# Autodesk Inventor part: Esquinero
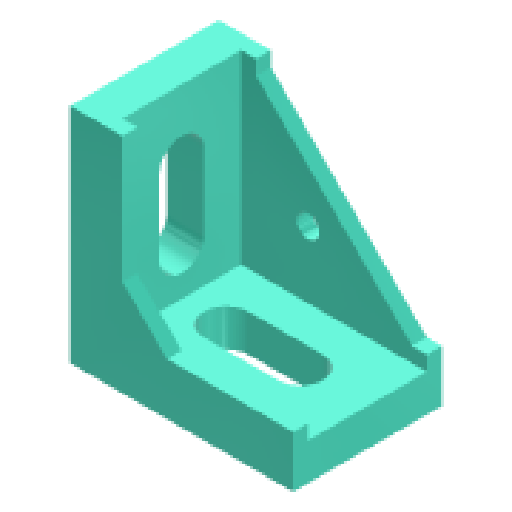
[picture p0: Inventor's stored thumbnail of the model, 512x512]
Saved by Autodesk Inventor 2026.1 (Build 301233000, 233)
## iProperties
Created: 2025-06
Part Number: Esquinero
Material: Genérico
Document SubType Name: Modeling
Designer: piero
Density: 1 g/cm^3
Appearance: Suave - Turquesa
Author: piero
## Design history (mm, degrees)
sketch "Boceto1"
  geometry: L1 (0, 0)-(30, 0); L2 (30, 0)-(30, -20); L3 (30, -20)-(0, -20); L4 (0, -20)-(0, 0); L5 (21, -10)-(11, -10); L6 (21, -7)-(11, -7); L7 (11, -13)-(21, -13); A1 r 3 centre (21, -10) between (21, -13) and (21, -7); A2 r 3 centre (11, -10) between (11, -7) and (11, -13); 5 further points
  constraints: 16 end point, 6 point on circle, 4 tangent, 3 midpoint, 3 parallel, 2 centre point, 2 horizontal, 1 perpendicular
  dimensions: "d0" = 30 distance of L2.end L3.end; "d1" = 20 distance of L1.end L2.end; "d2" = 10 distance of L5.start L5.end; "d3" = 6 diameter of A2; "d4" = 6 distance of point (24, -10) point (30, -10)
extrude "Extrusión1" new body sketch "Boceto1" distance "d6" = 5; taper "d7" = 0 deg
sketch "Boceto2"
  geometry: L1 (0, 0)-(20, 0) reference; L2 (0, 0)-(20, 0); L3 (20, 0)-(20, 5); L4 (20, 5)-(0, 5); L5 (0, 5)-(0, 0); 1 further point
  constraints: 8 end point, 2 parallel, 1 horizontal, 1 perpendicular
  dimensions: "d8" = 20 distance of L4.end L3.end; "d9" = 5 distance of L3.end L2.end
extrude "Extrusión2" join sketch "Boceto2" distance "d10" = 25; taper "d11" = 0 deg
sketch "Boceto3"
  geometry: L1 (6, 10)-(16, 10); L2 (6, 7)-(16, 7); L3 (16, 13)-(6, 13); L4 (25, 20)-(25, 0) reference; L5 (0, 0)-(25, 0) reference; A1 r 3 centre (6, 10) between (6, 13) and (6, 7); A2 r 3 centre (16, 10) between (16, 7) and (16, 13); 4 further points
  constraints: 8 end point, 5 point on circle, 4 tangent, 2 centre point, 2 midpoint, 1 horizontal, 1 parallel
  dimensions: "d12" = 10 distance of L1.start L1.end; "d13" = 6 diameter of A2; "d14" = 6 distance of point (25, 10) point (19, 10); "d15" = 10 distance from line of L5 point (11, 10)
extrude "Extrusión3" cut sketch "Boceto3" distance "d16" = 5; taper "d17" = 0 deg
sketch "Boceto4"
  geometry: L1 (5, 30)-(5, 5) reference; L2 (5, 5)-(30, 5) reference; L3 (5, 5)-(5, 28); L4 (5, 30)-(7, 30); L5 (7, 30)-(7, 28); L6 (30, 5)-(30, 7); L7 (30, 7)-(28, 7); L8 (28, 7)-(7, 28); 2 further points
  constraints: 12 end point, 3 perpendicular, 2 point on line, 1 horizontal, 1 vertical
  dimensions: "d18" = 2 distance of L3.end L1.start; "d19" = 2 distance of point (28, 5) L2.end; "d22" = 2 distance of L2.end L6.end
extrude "Extrusión4" join sketch "Boceto4" distance "d20" = 2; taper "d21" = 0 deg
sketch "Boceto5"
  geometry: L1 (-30, 0)-(-30, 5) reference; L2 (-30, 0)-(-30, 7) reference; L3 (-30, 5)-(-30, 7); L4 (-30, 7)-(-28, 7); L5 (-7, 30)-(-7, 28) reference; L6 (-28, 7)-(-7, 28); L7 (-7, 28)-(-7, 30); L8 (-7, 30)-(-5, 30); L9 (-5, 30)-(-5, 5); L10 (-5, 5)-(-30, 5); 1 further point
  constraints: 14 end point, 4 perpendicular, 1 collinear, 1 point on line, 1 vertical
  dimensions: "d23" = 2 distance of L2.end L4.end
extrude "Extrusión5" join sketch "Boceto5" distance "d24" = 2; taper "d25" = 0 deg
sketch "Boceto6"
  geometry: L1 (28, 7)-(7, 28) reference; L2 (7, 28)-(7, 13); L3 (7, 13)-(13, 7); L4 (13, 7)-(28, 7); 1 further point
  constraints: 6 end point, 1 perpendicular, 1 vertical
  dimensions: "d26" = 45 deg angle of L4 L3; "d27" = 15 distance of L3.end L1.start
extrude "Extrusión6" cut sketch "Boceto6" distance "d28" = 2; taper "d29" = 0 deg
sketch "Boceto7"
  geometry: L1 (7, 28)-(28, 7) reference; L2 (7, 28)-(7, 7); L3 (7, 7)-(28, 7); L4 (7, 7)-(17.5, 17.5); L5 (28, 7)-(7, 28) reference; 3 further points
  constraints: 6 end point, 2 midpoint, 1 perpendicular, 1 point on line, 1 vertical
  dimensions: "d30" = 5 distance of point (17.5, 17.5) point (13.964, 13.964)
hole "Agujero1" sketch "Boceto7" at (13.964, 13.964) diameter "d31" = 3; stored, may be unused: countersink angle "d35" = 90 deg, drill point angle "d37" = 118 deg; dims "d32" = 6, "d33" = 4, "d34" = 2, "d36" = 8
node "Sólido1"
